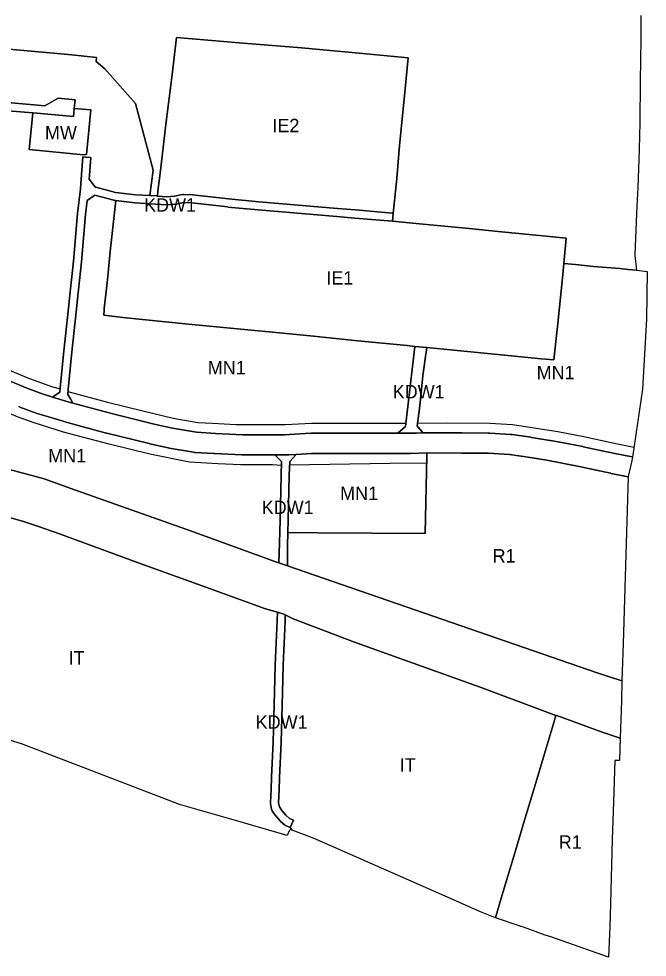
# Model space of a CAD drawing. Extents: x -284239 to -281592, y 34477 to 37267.
# Drawn here: x -282060 to -281592, y 34477 to 35176 of the extents above; entities that cross this region are included whole.
import ezdxf

# ---------------------------------------------------------------- set-up
doc = ezdxf.new("R2010")
doc.units = 0
for name, color, linetype in [('linie_rozgraniczajace', 7, 'Continuous'), ('linie_zabudowy_nieprzekraczalne', 7, 'Continuous'), ('oznaczenia_przeznaczen', 7, 'Continuous')]:
    doc.layers.add(name, color=color, linetype=linetype)

msp = doc.modelspace()

# ---------------------------------------------------------------- linework, layer by layer
at = {"layer": 'linie_rozgraniczajace'}
for points in [[(-281596.74, 35178.24), (-281596.78, 35160.96), (-281597.43, 35129.22), (-281597.69, 35098.67), (-281598.08, 35078.59), (-281599.15, 35050.02), (-281599.77, 35036.46), (-281600, 35030.79), (-281600.99, 35006.4), (-281601.38, 35000), (-281601.4, 34999.68), (-281600, 34988.64), (-281600.025, 34988.638), (-281606.191, 34989.281), (-281612.576, 34989.839), (-281631.97, 34991.515), (-281640.855, 34992.414), (-281645.378, 34992.872), (-281654.151, 34993.726), (-281652.274, 35012.446), (-281669.794, 35014.198), (-281703.01, 35017.337), (-281724.619, 35019.673), (-281766.741, 35023.688), (-281781.668, 35025.096), (-281781.108, 35030.982), (-281778.495, 35057.05), (-281776.305, 35081.433), (-281772.8, 35116.036), (-281769.88, 35146.697), (-281806.381, 35150.201), (-281849.38, 35154.216), (-281895.59, 35157.939), (-281942.239, 35161.808), (-281945.451, 35134.36), (-281950.196, 35097.201), (-281954.138, 35062.891), (-281956.182, 35047.414), (-281956.472, 35043.832), (-281957.26, 35043.899), (-281957.323, 35043.904), (-281962.246, 35044.211), (-281959.784, 35063.092), (-281972.748, 35112.702), (-281995.767, 35138.498), (-282002.132, 35143.954), (-282001.793, 35147.149), (-282020.291, 35148.902), (-282066.83, 35153.251)], [(-282066.83, 35153.251), (-282020.291, 35148.902), (-282001.793, 35147.149), (-282002.132, 35143.954), (-281995.767, 35138.498), (-281972.748, 35112.702), (-281959.784, 35063.092), (-281962.246, 35044.211), (-281972.798, 35044.868), (-281987.647, 35046.543), (-282002.349, 35050.471), (-282002.388, 35050.476), (-282002.452, 35050.496), (-282002.869, 35050.592), (-282002.982, 35050.856), (-282007.332, 35056.485), (-282007.135, 35059.479), (-282006.055, 35072.607), (-282009.843, 35072.919), (-282012.035, 35073.099), (-282013.116, 35059.946), (-282013.119, 35059.902), (-282013.81, 35049.337), (-282015.898, 35030.824), (-282015.903, 35030.764), (-282019.035, 34995.417), (-282021.375, 34972.565), (-282022.618, 34960.434), (-282026.432, 34926.113), (-282026.435, 34926.079), (-282028.899, 34900.909), (-282029.243, 34897.901), (-282034.474, 34894.191), (-282036.672, 34894.822), (-282041.5, 34896.38), (-282052.947, 34900.568), (-282072.117, 34908.385)], [(-282076.923, 35108.158), (-282049.199, 35105.852), (-282049.213, 35105.69), (-282051.859, 35078.438), (-282011.642, 35074.469), (-282009.261, 35074.866), (-282005.953, 35108.071), (-282018.521, 35109.13), (-282017.805, 35115.59), (-282030.253, 35116.738), (-282040.199, 35111.068), (-282045.826, 35111.592), (-282076.453, 35114.14)], [(-282076.453, 35114.14), (-282045.826, 35111.592), (-282040.199, 35111.068), (-282030.253, 35116.738), (-282017.805, 35115.59), (-282018.521, 35109.13), (-282018.679, 35109.063), (-282018.495, 35109.046), (-282019.052, 35103.072), (-282046.354, 35105.615), (-282049.199, 35105.852), (-282076.923, 35108.158)], [(-282072.117, 34908.385), (-282052.947, 34900.568), (-282041.5, 34896.38), (-282036.672, 34894.822), (-282034.474, 34894.191), (-282022.237, 34890.424), (-282019.359, 34889.643), (-281997.203, 34883.63), (-281990.673, 34881.864), (-281958.978, 34874.096), (-281945.23, 34870.967), (-281927.552, 34867.938), (-281913.332, 34867.056), (-281892.946, 34866.155), (-281861.956, 34866.099), (-281842.76, 34867.208), (-281842.312, 34867.133), (-281841.786, 34867.237), (-281808.28, 34867.18), (-281777.538, 34867.224), (-281772.538, 34867.231), (-281770.242, 34867.234), (-281768.365, 34867.237), (-281763.944, 34867.362), (-281758.946, 34867.503), (-281756.659, 34867.568), (-281756.302, 34867.503), (-281755.919, 34867.578), (-281730.276, 34867.522), (-281730.014, 34867.47), (-281729.756, 34867.52), (-281710.206, 34867.409), (-281709.662, 34867.299), (-281709.219, 34867.372), (-281693.483, 34866.323), (-281693.332, 34866.288), (-281692.621, 34866.237), (-281678.629, 34864.222), (-281678.486, 34864.183), (-281678.24, 34864.163), (-281664.476, 34861.925), (-281664.279, 34861.869), (-281664.017, 34861.844), (-281655.593, 34860.239), (-281640.059, 34857.278), (-281639.839, 34857.212), (-281639.622, 34857.189), (-281616.135, 34852.108), (-281603.167, 34849.56), (-281602.977, 34849.519), (-281602.99, 34849.43), (-281603.842, 34845.614), (-281606.23, 34834.92), (-281606.231, 34834.896), (-281618.979, 34837.376), (-281619.177, 34837.435), (-281619.369, 34837.456), (-281642.834, 34842.533), (-281666.842, 34847.108), (-281680.681, 34849.359), (-281694.564, 34851.358), (-281710.277, 34852.405), (-281730.078, 34852.518), (-281755.969, 34852.574), (-281756.085, 34852.574), (-281767.778, 34852.244), (-281768.119, 34852.306), (-281768.488, 34852.233), (-281808.023, 34852.176), (-281808.282, 34852.228), (-281808.541, 34852.177), (-281836.089, 34852.223), (-281841.844, 34852.233), (-281853.316, 34851.49), (-281853.409, 34851.484), (-281858.756, 34851.255), (-281861.031, 34851.123), (-281861.48, 34851.199), (-281862.007, 34851.095), (-281864.617, 34851.099), (-281868.837, 34851.095), (-281869.197, 34851.096), (-281892.887, 34851.151), (-281893.332, 34851.24), (-281893.724, 34851.17), (-281913.844, 34852.06), (-281914.205, 34852.14), (-281914.479, 34852.094), (-281928.678, 34852.975), (-281928.879, 34853.021), (-281929.792, 34853.099), (-281947.827, 34856.189), (-281948.158, 34856.285), (-281948.499, 34856.323), (-281962.266, 34859.457), (-281962.484, 34859.526), (-281962.636, 34859.545), (-281994.226, 34867.287)], [(-282059.691, 34887.063), (-282059.263, 34886.978), (-282058.933, 34886.767), (-282046.755, 34882.268), (-282046.7, 34882.258), (-282046.073, 34882.034), (-282026.665, 34876.127), (-282026.553, 34876.11), (-282026.231, 34876), (-282008.361, 34871.055), (-282008.26, 34871.041), (-282008.051, 34870.97), (-281994.623, 34867.389), (-281994.482, 34867.37), (-281994.226, 34867.287), (-281962.636, 34859.545), (-281962.484, 34859.526), (-281962.266, 34859.457), (-281948.499, 34856.323), (-281948.158, 34856.285), (-281947.827, 34856.189), (-281929.792, 34853.099), (-281928.879, 34853.021), (-281928.678, 34852.975), (-281914.479, 34852.094), (-281914.205, 34852.14), (-281913.844, 34852.06), (-281893.724, 34851.17), (-281893.332, 34851.24), (-281892.887, 34851.151), (-281869.197, 34851.096), (-281864.099, 34846.081), (-281864.462, 34835.894), (-281865.257, 34802.818), (-281865.76, 34785.652), (-281865.721, 34785.586), (-281865.728, 34785.386), (-281866.249, 34770.806), (-281869.034, 34771.77), (-281931.048, 34794.25), (-282020.246, 34825.855), (-282040.771, 34833.185), (-282079.627, 34843.782)], [(-281994.226, 34867.287), (-281994.482, 34867.37), (-281994.623, 34867.389), (-282008.051, 34870.97), (-282008.26, 34871.041), (-282008.361, 34871.055), (-282026.231, 34876), (-282026.553, 34876.11), (-282026.665, 34876.127), (-282046.073, 34882.034), (-282046.7, 34882.258), (-282046.755, 34882.268), (-282058.933, 34886.767), (-282059.263, 34886.978), (-282059.691, 34887.063)], [(-282079.627, 34843.782), (-282040.771, 34833.185), (-282020.246, 34825.855), (-281931.048, 34794.25), (-281869.034, 34771.77), (-281866.249, 34770.806), (-281859.76, 34768.562), (-281629.249, 34688.827), (-281610.885, 34682.95), (-281610.847, 34682.938), (-281611.32, 34667.99), (-281612.231, 34640.087), (-281625.632, 34644.771), (-281659.302, 34657.074), (-281660.005, 34656.979), (-281660.074, 34657.005), (-281716.458, 34678.055), (-281809.795, 34711.676), (-281855.459, 34728.988), (-281861.354, 34732.069), (-281862.339, 34732.584), (-281867.285, 34733.948), (-281876.211, 34736.411), (-281920.401, 34752.534), (-281971.995, 34771.319), (-282029.41, 34792.287), (-282045.021, 34797.778), (-282056.794, 34801.878), (-282070.024, 34805.451)], [(-282070.024, 34805.451), (-282056.794, 34801.878), (-282045.021, 34797.778), (-282029.41, 34792.287), (-281971.995, 34771.319), (-281920.401, 34752.534), (-281876.211, 34736.411), (-281867.285, 34733.948), (-281867.533, 34727.593), (-281869.013, 34694.805), (-281869.008, 34694.774), (-281869.016, 34694.737), (-281869.471, 34674.353), (-281870.097, 34646.307), (-281870.437, 34637.459), (-281871.632, 34611.095), (-281871.975, 34601.863), (-281872.373, 34592.018), (-281872.363, 34591.961), (-281872.376, 34591.897), (-281872.32, 34591.324), (-281871.523, 34587.225), (-281871.35, 34586.649), (-281871.088, 34586.153), (-281868.924, 34582.851), (-281868.761, 34582.651), (-281868.702, 34582.554), (-281865.514, 34578.796), (-281865.348, 34578.616), (-281865.244, 34578.547), (-281865.185, 34578.465), (-281861.883, 34575.618), (-281861.251, 34575.229), (-281861.117, 34575.138), (-281857.7, 34573.657), (-281856.295, 34571.74), (-281857.38, 34572.16), (-281858.37, 34571.18), (-281859.89, 34567.72), (-281873.62, 34571.7), (-281896.8, 34578.41), (-281939.97, 34590.72), (-282000, 34613.85), (-282057.54, 34636.03), (-282140.42, 34661.16)]]:
    msp.add_lwpolyline(points, dxfattribs=at)
for points in [[(-281956.472, 35043.832), (-281956.182, 35047.414), (-281954.138, 35062.891), (-281950.196, 35097.201), (-281945.451, 35134.36), (-281942.239, 35161.808), (-281895.59, 35157.939), (-281849.38, 35154.216), (-281806.381, 35150.201), (-281769.88, 35146.697), (-281772.8, 35116.036), (-281776.305, 35081.433), (-281778.495, 35057.05), (-281781.108, 35030.982), (-281781.778, 35031.146), (-281809.177, 35033.481), (-281822.616, 35034.506), (-281848.731, 35036.725), (-281881.119, 35039.628), (-281903.519, 35041.675), (-281930.305, 35044.689), (-281930.458, 35044.698), (-281930.486, 35044.704), (-281937.091, 35045.045), (-281937.163, 35045.033), (-281937.246, 35045.049), (-281937.845, 35044.989), (-281943.834, 35043.769), (-281949.555, 35043.239)], [(-282051.859, 35078.438), (-282049.213, 35105.69), (-282049.199, 35105.852), (-282046.354, 35105.615), (-282019.052, 35103.072), (-282018.495, 35109.046), (-282018.679, 35109.063), (-282018.521, 35109.13), (-282005.953, 35108.071), (-282009.261, 35074.866), (-282011.642, 35074.469)], [(-282034.474, 34894.191), (-282029.243, 34897.901), (-282028.899, 34900.909), (-282026.435, 34926.079), (-282026.432, 34926.113), (-282022.618, 34960.434), (-282021.375, 34972.565), (-282019.035, 34995.417), (-282015.903, 35030.764), (-282015.898, 35030.824), (-282013.81, 35049.337), (-282013.119, 35059.902), (-282013.116, 35059.946), (-282012.035, 35073.099), (-282009.843, 35072.919), (-282006.055, 35072.607), (-282007.135, 35059.479), (-282007.332, 35056.485), (-282002.982, 35050.856), (-282002.869, 35050.592), (-282002.452, 35050.496), (-282002.388, 35050.476), (-282002.349, 35050.471), (-281987.647, 35046.543), (-281972.798, 35044.868), (-281962.246, 35044.211), (-281957.323, 35043.904), (-281957.26, 35043.899), (-281956.472, 35043.832), (-281949.555, 35043.239), (-281943.834, 35043.769), (-281937.845, 35044.989), (-281937.246, 35045.049), (-281937.163, 35045.033), (-281937.091, 35045.045), (-281930.486, 35044.704), (-281930.458, 35044.698), (-281930.305, 35044.689), (-281903.519, 35041.675), (-281881.119, 35039.628), (-281848.731, 35036.725), (-281822.616, 35034.506), (-281809.177, 35033.481), (-281781.778, 35031.146), (-281781.108, 35030.982), (-281781.668, 35025.096), (-281809.661, 35027.5), (-281823.099, 35028.526), (-281849.251, 35030.748), (-281881.66, 35033.653), (-281904.104, 35035.704), (-281904.159, 35035.709), (-281930.886, 35038.716), (-281937.02, 35039.034), (-281942.796, 35037.857), (-281943.015, 35037.835), (-281943.118, 35037.81), (-281949.268, 35037.24), (-281949.544, 35037.227), (-281949.801, 35037.238), (-281957.737, 35037.919), (-281973.26, 35038.888), (-281973.396, 35038.897), (-281987.512, 35040.49), (-281988.542, 35040.606), (-281988.741, 35040.657), (-281988.98, 35040.688), (-282003.127, 35044.468), (-282008.771, 35040.571), (-282009.931, 35030.192), (-282013.061, 34994.863), (-282013.064, 34994.827), (-282016.628, 34960.036), (-282016.653, 34959.795), (-282020.466, 34925.47), (-282022.986, 34899.725), (-282023.277, 34896.135), (-282021.271, 34892.786), (-282019.359, 34889.643), (-282022.237, 34890.424)], [(-282023.277, 34896.135), (-282022.986, 34899.725), (-282020.466, 34925.47), (-282016.653, 34959.795), (-282016.628, 34960.036), (-282013.064, 34994.827), (-282013.061, 34994.863), (-282009.931, 35030.192), (-282008.771, 35040.571), (-282003.127, 35044.468), (-281988.98, 35040.688), (-281988.741, 35040.657), (-281988.542, 35040.606), (-281987.512, 35040.49), (-281991.588, 35002.518), (-281993.632, 34981.493), (-281996.041, 34960.103), (-281996.113, 34958.88), (-281996.333, 34955.139), (-281982.171, 34953.533), (-281965.088, 34951.635), (-281935.887, 34948.715), (-281883.983, 34943.678), (-281873.251, 34942.729), (-281840.473, 34939.444), (-281807.476, 34936.086), (-281770.61, 34932.508), (-281764.972, 34931.951), (-281771.896, 34872.357), (-281777.538, 34867.224), (-281808.28, 34867.18), (-281841.786, 34867.237), (-281842.312, 34867.133), (-281842.76, 34867.208), (-281861.956, 34866.099), (-281892.946, 34866.155), (-281913.332, 34867.056), (-281927.552, 34867.938), (-281945.23, 34870.967), (-281958.978, 34874.096), (-281990.673, 34881.864), (-281997.203, 34883.63), (-282019.359, 34889.643), (-282021.271, 34892.786)], [(-281996.333, 34955.139), (-281996.113, 34958.88), (-281996.041, 34960.103), (-281993.632, 34981.493), (-281991.588, 35002.518), (-281987.512, 35040.49), (-281973.396, 35038.897), (-281973.26, 35038.888), (-281957.737, 35037.919), (-281949.801, 35037.238), (-281949.544, 35037.227), (-281949.268, 35037.24), (-281943.118, 35037.81), (-281943.015, 35037.835), (-281942.796, 35037.857), (-281937.02, 35039.034), (-281930.886, 35038.716), (-281904.159, 35035.709), (-281904.104, 35035.704), (-281881.66, 35033.653), (-281849.251, 35030.748), (-281823.099, 35028.526), (-281809.661, 35027.5), (-281781.668, 35025.096), (-281766.741, 35023.688), (-281724.619, 35019.673), (-281703.01, 35017.337), (-281669.794, 35014.198), (-281652.274, 35012.446), (-281654.151, 34993.726), (-281654.975, 34985.508), (-281658.698, 34948.934), (-281661.472, 34921.777), (-281671.073, 34922.709), (-281698.338, 34925.354), (-281735.934, 34929.077), (-281756.045, 34931.067), (-281764.972, 34931.951), (-281770.61, 34932.508), (-281807.476, 34936.086), (-281840.473, 34939.444), (-281873.251, 34942.729), (-281883.983, 34943.678), (-281935.887, 34948.715), (-281965.088, 34951.635), (-281982.171, 34953.533)], [(-281763.334, 34872.696), (-281761.492, 34885.693), (-281760.542, 34895.122), (-281759.05, 34909.93), (-281757.234, 34922.699), (-281756.045, 34931.067), (-281735.934, 34929.077), (-281698.338, 34925.354), (-281671.073, 34922.709), (-281661.472, 34921.777), (-281658.698, 34948.934), (-281654.975, 34985.508), (-281654.151, 34993.726), (-281645.378, 34992.872), (-281640.855, 34992.414), (-281631.97, 34991.515), (-281612.576, 34989.839), (-281606.191, 34989.281), (-281600.025, 34988.638), (-281600, 34988.64), (-281592.08, 34987.73), (-281592.66, 34952.08), (-281595.49, 34900.07), (-281602.977, 34849.519), (-281603.167, 34849.56), (-281616.135, 34852.108), (-281639.622, 34857.189), (-281639.839, 34857.212), (-281640.059, 34857.278), (-281655.593, 34860.239), (-281664.017, 34861.844), (-281664.279, 34861.869), (-281664.476, 34861.925), (-281678.24, 34864.163), (-281678.486, 34864.183), (-281678.629, 34864.222), (-281692.621, 34866.237), (-281693.332, 34866.288), (-281693.483, 34866.323), (-281709.219, 34867.372), (-281709.662, 34867.299), (-281710.206, 34867.409), (-281729.756, 34867.52), (-281730.014, 34867.47), (-281730.276, 34867.522), (-281755.919, 34867.578), (-281756.302, 34867.503), (-281756.659, 34867.568), (-281758.946, 34867.503)], [(-281777.538, 34867.224), (-281771.896, 34872.357), (-281764.972, 34931.951), (-281756.045, 34931.067), (-281757.234, 34922.699), (-281759.05, 34909.93), (-281760.542, 34895.122), (-281761.492, 34885.693), (-281763.334, 34872.696), (-281758.946, 34867.503), (-281763.944, 34867.362), (-281768.365, 34867.237), (-281770.242, 34867.234), (-281772.538, 34867.231)], [(-281869.197, 34851.096), (-281868.837, 34851.095), (-281864.617, 34851.099), (-281862.007, 34851.095), (-281861.48, 34851.199), (-281861.031, 34851.123), (-281858.756, 34851.255), (-281853.409, 34851.484), (-281853.316, 34851.49), (-281858.066, 34846.251), (-281858.461, 34835.914), (-281858.472, 34835.859), (-281858.462, 34835.805), (-281859.26, 34802.659), (-281859.535, 34793.258), (-281859.812, 34783.755), (-281859.759, 34783.74), (-281859.76, 34768.562), (-281866.249, 34770.806), (-281865.728, 34785.386), (-281865.721, 34785.586), (-281865.76, 34785.652), (-281865.257, 34802.818), (-281864.462, 34835.894), (-281864.099, 34846.081)], [(-281859.812, 34783.755), (-281859.535, 34793.258), (-281837.266, 34793.127), (-281757.219, 34792.658), (-281756, 34850.075), (-281755.969, 34852.574), (-281730.078, 34852.518), (-281710.277, 34852.405), (-281694.564, 34851.358), (-281680.681, 34849.359), (-281666.842, 34847.108), (-281642.834, 34842.533), (-281619.369, 34837.456), (-281619.177, 34837.435), (-281618.979, 34837.376), (-281606.231, 34834.896), (-281608.61, 34760.33), (-281609.03, 34743.69), (-281609.97, 34710.62), (-281610.847, 34682.938), (-281610.885, 34682.95), (-281629.249, 34688.827), (-281859.76, 34768.562), (-281859.759, 34783.74)], [(-281859.535, 34793.258), (-281859.26, 34802.659), (-281858.462, 34835.805), (-281858.472, 34835.859), (-281858.461, 34835.914), (-281858.066, 34846.251), (-281853.316, 34851.49), (-281841.844, 34852.233), (-281836.089, 34852.223), (-281808.541, 34852.177), (-281808.282, 34852.228), (-281808.023, 34852.176), (-281768.488, 34852.233), (-281768.119, 34852.306), (-281767.778, 34852.244), (-281756.085, 34852.574), (-281755.969, 34852.574), (-281756, 34850.075), (-281757.219, 34792.658), (-281837.266, 34793.127)], [(-281872.376, 34591.897), (-281872.363, 34591.961), (-281872.373, 34592.018), (-281871.975, 34601.863), (-281871.632, 34611.095), (-281870.437, 34637.459), (-281870.097, 34646.307), (-281869.471, 34674.353), (-281869.016, 34694.737), (-281869.008, 34694.774), (-281869.013, 34694.805), (-281867.533, 34727.593), (-281867.285, 34733.948), (-281862.339, 34732.584), (-281861.354, 34732.069), (-281861.54, 34727.335), (-281863.018, 34694.569), (-281863.472, 34674.219), (-281864.099, 34646.149), (-281864.102, 34646.112), (-281864.443, 34637.208), (-281865.638, 34610.848), (-281865.98, 34601.631), (-281866.364, 34592.126), (-281865.746, 34588.948), (-281864.007, 34586.294), (-281861.09, 34582.857), (-281858.311, 34580.461), (-281855.315, 34579.162), (-281857.7, 34573.657), (-281861.117, 34575.138), (-281861.251, 34575.229), (-281861.883, 34575.618), (-281865.185, 34578.465), (-281865.244, 34578.547), (-281865.348, 34578.616), (-281865.514, 34578.796), (-281868.702, 34582.554), (-281868.761, 34582.651), (-281868.924, 34582.851), (-281871.088, 34586.153), (-281871.35, 34586.649), (-281871.523, 34587.225), (-281872.32, 34591.324)], [(-281866.364, 34592.126), (-281865.98, 34601.631), (-281865.638, 34610.848), (-281864.443, 34637.208), (-281864.102, 34646.112), (-281864.099, 34646.149), (-281863.472, 34674.219), (-281863.018, 34694.569), (-281861.54, 34727.335), (-281861.354, 34732.069), (-281855.459, 34728.988), (-281809.795, 34711.676), (-281716.458, 34678.055), (-281660.074, 34657.005), (-281662.108, 34650.178), (-281668.861, 34627.653), (-281675.81, 34604.34), (-281683.352, 34579.153), (-281690.4, 34555.544), (-281700.701, 34520.993), (-281705.074, 34506.447), (-281716.05, 34510.9), (-281742.38, 34522.62), (-281839.81, 34565.35), (-281856.295, 34571.74), (-281857.7, 34573.657), (-281855.315, 34579.162), (-281858.311, 34580.461), (-281861.09, 34582.857), (-281864.007, 34586.294), (-281865.746, 34588.948)], [(-281705.074, 34506.447), (-281700.701, 34520.993), (-281690.4, 34555.544), (-281683.352, 34579.153), (-281675.81, 34604.34), (-281668.861, 34627.653), (-281662.108, 34650.178), (-281660.074, 34657.005), (-281660.005, 34656.979), (-281659.302, 34657.074), (-281625.632, 34644.771), (-281612.231, 34640.087), (-281612.77, 34623.56), (-281616.22, 34623.58), (-281617.28, 34592.68), (-281618.16, 34564.76), (-281619.39, 34517.15), (-281620.01, 34500), (-281620.85, 34477.06), (-281663.83, 34492.28), (-281667.96, 34493.6), (-281684.01, 34499.37), (-281685.75, 34500), (-281704.91, 34506.38)]]:
    msp.add_lwpolyline(points, close=True, dxfattribs=at)
at = {"layer": 'linie_zabudowy_nieprzekraczalne'}
for points in [[(-282198.123, 35064.261), (-282196.239, 35047.351), (-282196.636, 35024.993), (-282199.679, 35012.161), (-282204.97, 34998.204), (-282214.76, 34979.551), (-282213.569, 34975.45), (-282199.017, 34969.364), (-282157.081, 34951.703), (-282097.946, 34927.428), (-282069.636, 34915.522), (-282053.628, 34908.775), (-282035.372, 34902.16), (-282028.954, 34900.342)], [(-281864.196, 34843.326), (-281870.933, 34843.753), (-281894.481, 34843.621), (-281911.547, 34844.349), (-281932.714, 34845.804), (-281962.215, 34851.691), (-281992.509, 34859.099), (-282026.376, 34868.161), (-282048.204, 34874.908), (-282060.243, 34879.274), (-282084.452, 34889.262), (-282116.335, 34902.623), (-282157.478, 34919.424)], [(-282023.122, 34898.337), (-281993.568, 34890.254), (-281967.374, 34883.838), (-281944.884, 34878.414), (-281926.496, 34875.239), (-281915.516, 34874.776), (-281898.053, 34873.717), (-281886.411, 34873.717), (-281861.276, 34873.717), (-281841.961, 34874.71), (-281804.39, 34874.643), (-281771.616, 34874.768)], [(-281763.03, 34874.837), (-281741.023, 34875.04), (-281709.14, 34874.842), (-281692.207, 34873.85), (-281658.605, 34868.558), (-281639.158, 34864.722), (-281616.668, 34859.827), (-281601.851, 34856.916)], [(-281756.104, 34845.01), (-281783.356, 34844.613), (-281858.305, 34843.492)]]:
    msp.add_lwpolyline(points, dxfattribs=at)

# ---------------------------------------------------------------- texts
at = {"layer": 'oznaczenia_przeznaczen'}
for s, p in [('IE2', (-281870.952, 35091.351)), ('MW', (-282040.184, 35086.069)), ('KDW1', (-281966.429, 35032.227)), ('IE1', (-281830.788, 34977.904)), ('MN1', (-281919.006, 34911.107)), ('MN1', (-281674.348, 34907.421)), ('KDW1', (-281781.45, 34893.145)), ('MN1', (-282037.783, 34845.521)), ('MN1', (-281820.542, 34817.488)), ('KDW1', (-281878.912, 34807.043)), ('R1', (-281707.121, 34770.981)), ('IT', (-282022.608, 34694.986)), ('KDW1', (-281883.405, 34647.161)), ('IT', (-281776.161, 34615.157)), ('R1', (-281657.863, 34557.808))]:
    msp.add_text(s, height=10, dxfattribs=at).set_placement(p)

doc.saveas('drawing.dxf')
